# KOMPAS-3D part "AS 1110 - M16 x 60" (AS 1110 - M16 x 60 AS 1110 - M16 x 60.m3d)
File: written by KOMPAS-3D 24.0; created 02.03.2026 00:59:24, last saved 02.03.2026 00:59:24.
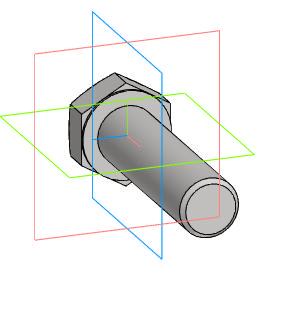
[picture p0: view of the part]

Document properties: Автор: R2D2; Полное имя файла: E:\Работа\Зайцев\GVWR3131M-2W-F-S Задвижка клиновая с выдвижным штоком DN.ru Ду50-200 Ру63\DN100\исходные материалы\AS 1110 - M16 x 60 AS 1110 - M16 x 60.m3d

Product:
- Body: Solid1  | qty 1
- Part/product: AS 1110 - M16 x 60
    Комментарий: Болты и винты   шестигранные точные   метрические ISO
    additional columns: Сталь, мягкая

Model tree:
1. Solid1  (labels: Solid1)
